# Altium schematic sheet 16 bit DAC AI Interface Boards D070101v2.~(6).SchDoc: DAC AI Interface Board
size B; Engineer: J. Heefner; DocumentNumber: D070101; Revision: 01; SheetNumber: 1; SheetTotal: 1; PageSetup: Record=PageOptions¦CenterHorizontal=True¦CenterVertical=True¦PrintScale=1.12¦XCorrection=1.00¦YCorrection=1.00¦PrintKind=0¦BorderSize=5000000¦LeftOffset=0¦BottomOffset=0¦Orientation=2¦PaperLength=1000¦PaperWidth=1000¦Scale=100¦PaperSource=15¦PrintQuality=1200¦MediaType=1¦DitherType=10¦PaperKind=Tabloid¦PrintScaleMode=1
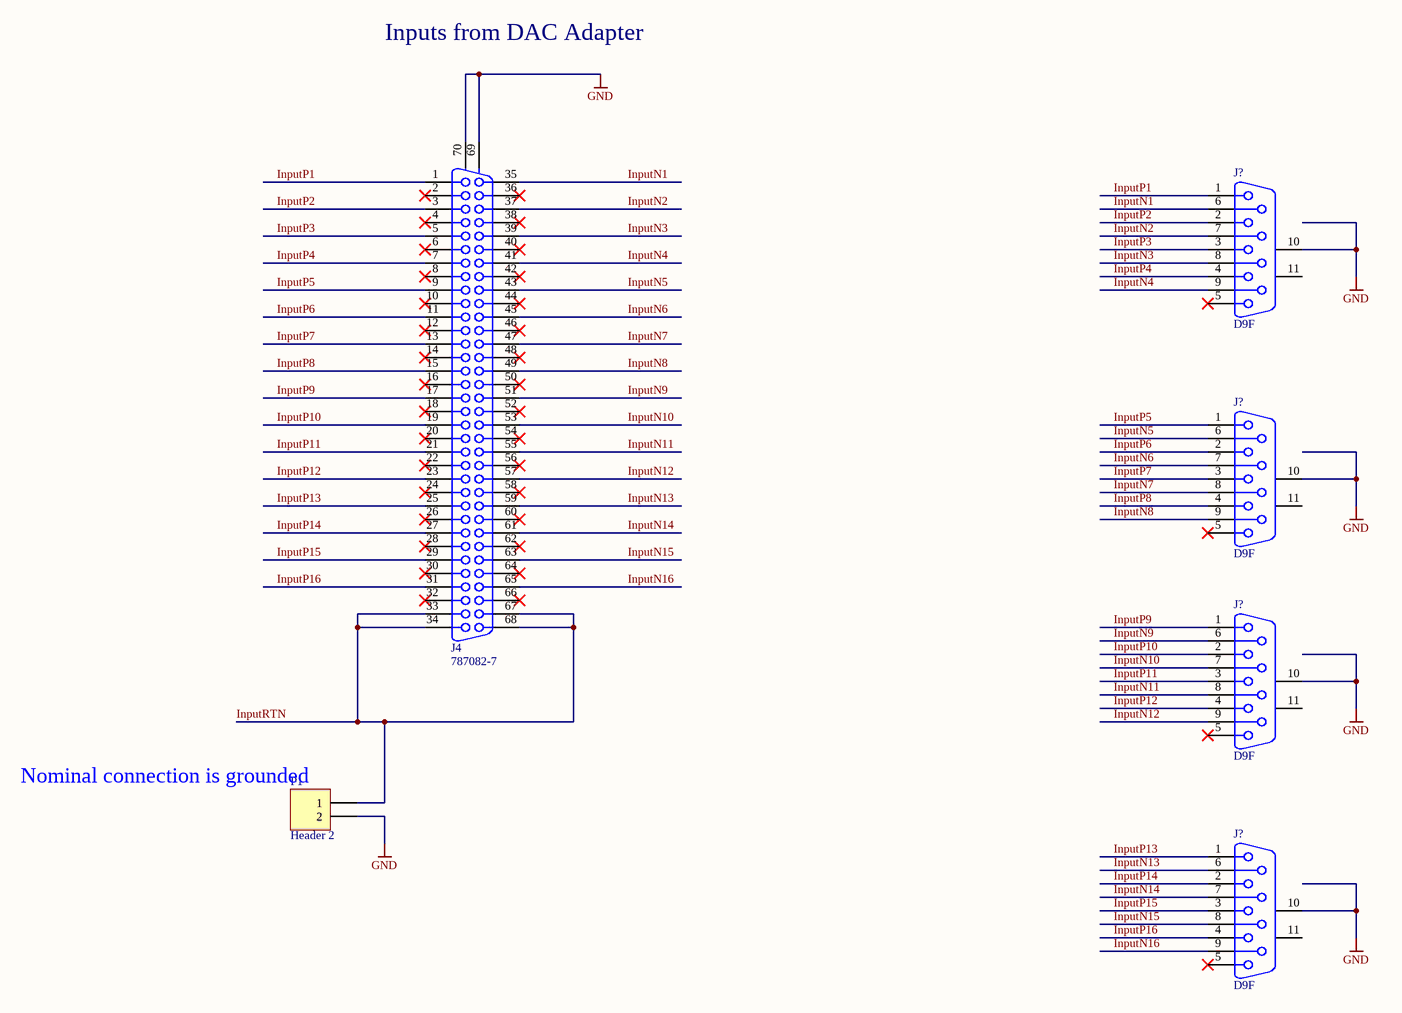
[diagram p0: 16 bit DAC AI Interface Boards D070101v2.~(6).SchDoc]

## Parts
(Parts that share a designator on the sheet are numbered #1, #2 ... from top to bottom, then left to right.)
J4  787082-7  [787082-7]
J?#1  D9F  [D9F]
J?#2  D9F  [D9F]
J?#3  D9F  [D9F]
J?#4  D9F  [D9F]
P1  Header 2  [HDR1X2]

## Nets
GND: J4.69(MH1) J4.70(MH2) J?#1.10(MH1) J?#2.10(MH1) J?#3.10(MH1) J?#4.10(MH1) P1.2
InputN1: J4.35 J?#1.6
InputN2: J4.37 J?#1.7
InputN3: J4.39 J?#1.8
InputN4: J4.41 J?#1.9
InputN5: J4.43 J?#2.6
InputN6: J4.45 J?#2.7
InputN7: J4.47 J?#2.8
InputN8: J4.49 J?#2.9
InputN9: J4.51 J?#3.6
InputN10: J4.53 J?#3.7
InputN11: J4.55 J?#3.8
InputN12: J4.57 J?#3.9
InputN13: J4.59 J?#4.6
InputN14: J4.61 J?#4.7
InputN15: J4.63 J?#4.8
InputN16: J4.65 J?#4.9
InputP1: J4.1 J?#1.1
InputP2: J4.3 J?#1.2
InputP3: J4.5 J?#1.3
InputP4: J4.7 J?#1.4
InputP5: J4.9 J?#2.1
InputP6: J4.11 J?#2.2
InputP7: J4.13 J?#2.3
InputP8: J4.15 J?#2.4
InputP9: J4.17 J?#3.1
InputP10: J4.19 J?#3.2
InputP11: J4.21 J?#3.3
InputP12: J4.23 J?#3.4
InputP13: J4.25 J?#4.1
InputP14: J4.27 J?#4.2
InputP15: J4.29 J?#4.3
InputP16: J4.31 J?#4.4
InputRTN: J4.33 J4.34 J4.67 J4.68 P1.1

Not connected (* = marked no-connect by the designer): J4 2* 4* 6* 8* 10* 12* 14* 16* 18* 20* 22* 24* 26* 28* 30* 32* 36* 38* 40* 42* 44* 46* 48* 50* 52* 54* 56* 58* 60* 62* 64* 66*; J?#1 5* 11(MH2); J?#2 5* 11(MH2); J?#3 5* 11(MH2); J?#4 5* 11(MH2)

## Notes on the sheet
- Inputs from DAC Adapter
- (near P1) Nominal connection is grounded

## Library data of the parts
J4 = D68F 90deg: CONN D-TYPE RCPT 68POS R/A SLDR; Manufacturer: TE Connectivity; Manufacturer Part Number: 7870827; Plating: Bright,Copper; Voltage Rating: 30V; Current Rating: 1A; Gender: Female; Number of Positions: 68; Connector Type: Receptacle,Connector; Number of Ports: 1; Shielding: Shielded; Mating Alignment: No (Without); Mating Connector Lock: Yes (With); PCB Mount Retention: With; PCB Mounting Orientation: Right Angle; Pitch: 0.05inch; PCB Thickness: 1.57mm; Contact Post Length: 0.1inch; Hole Diameter: 0.109inch; Approvals: UL
J?#1-J?#4 = D9F: Manufacturer: AMP - TE CONNECTIVITY; Manufacturer Part Number: 5747844-6
P1 = Header 2: Header, 2-Pin; Manufacturer: Molex; Number of Positions: 2; Gender: Male; Contact Resistance: 10mR; Max Current Rating: 4A; Voltage Rating: 250V; Insulation Resistance: 500GR; Pitch: 2.54mm; Approvals: UL,CSA; Glow Wire Compliant: Non-compliant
